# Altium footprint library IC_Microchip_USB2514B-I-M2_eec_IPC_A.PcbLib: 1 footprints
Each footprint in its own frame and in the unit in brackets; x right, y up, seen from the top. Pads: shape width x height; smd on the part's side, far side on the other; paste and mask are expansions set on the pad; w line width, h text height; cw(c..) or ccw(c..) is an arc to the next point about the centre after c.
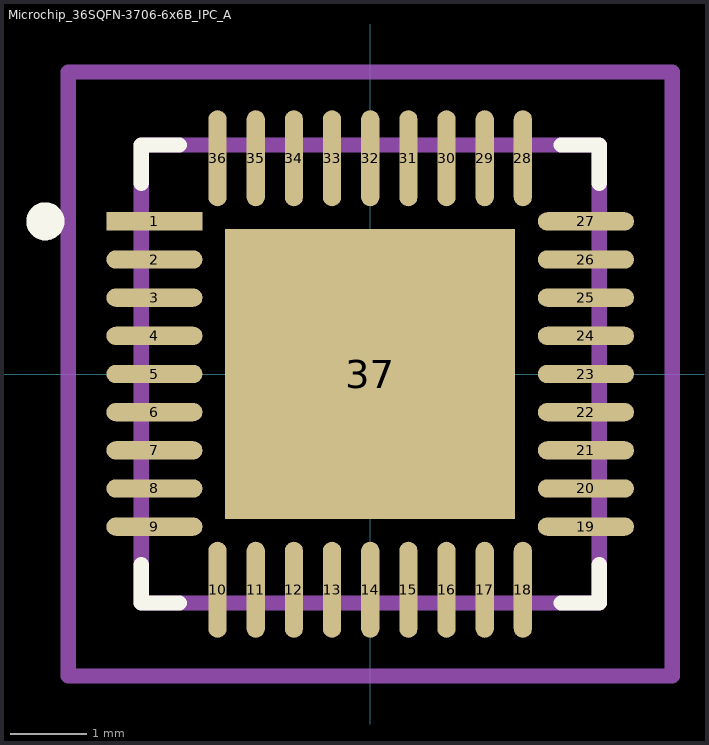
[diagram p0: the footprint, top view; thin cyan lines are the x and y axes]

## Microchip_36SQFN-3706-6x6B_IPC_A [mm]
pads (37):
  rect 1.259x0.239 smd paste+0 mask+0: 1(-2.827,2)
  rrect100% 1.259x0.239 smd paste+0 mask+0: 2(-2.827,1.5) 3(-2.827,1) 4(-2.827,0.5) 5(-2.827,0) 6(-2.827,-0.5) 7(-2.827,-1) 8(-2.827,-1.5) 9(-2.827,-2) 19(2.827,-2) 20(2.827,-1.5) 21(2.827,-1) 22(2.827,-0.5) 23(2.827,0) 24(2.827,0.5) 25(2.827,1) 26(2.827,1.5) 27(2.827,2)
  rrect100% 0.239x1.259 smd paste+0 mask+0: 10(-2,-2.827) 11(-1.5,-2.827) 12(-1,-2.827) 13(-0.5,-2.827) 14(0,-2.827) 15(0.5,-2.827) 16(1,-2.827) 17(1.5,-2.827) 18(2,-2.827) 28(2,2.827) 29(1.5,2.827) 30(1,2.827) 31(0.5,2.827) 32(0,2.827) 33(-0.5,2.827) 34(-1,2.827) 35(-1.5,2.827) 36(-2,2.827)
  rect 3.8x3.8 smd paste-1000 mask+0: 37(0,0)
Top Overlay:
  circle w0.25: c-4.256,2 r0.125
  lines w0.2: -3,-2.5 -3,-3 -2.5,-3 ; -3,2.5 -3,3 -2.5,3 ; 2.5,-3 3,-3 3,-2.5 ; 2.5,3 3,3 3,2.5
Top Paste:
  rectangle: -1.202,-1.202 1.202,1.202
Mechanical 10:
  lines w0.2: -3.956,-3.956 3.956,-3.956 3.956,3.956 -3.956,3.956 -3.956,-3.956
  text ".Designator" at 0,0.188 h1
Mechanical 12:
  lines w0.2: -3,-3 3,-3 3,3 -3,3 -3,-3
Mechanical 15:
  lines w0.1: -0.5,0 0.5,0 ; 0,-0.5 0,0.5
  lines w0.2: -3.956,-3.956 3.956,-3.956 3.956,3.956 -3.956,3.956 -3.956,-3.956
3D body "IC_Microchip_USB2514B-I-M2_eec.STEP": height 0.25, standoff 0, extent -3.956,-3.956 3.956,3.956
